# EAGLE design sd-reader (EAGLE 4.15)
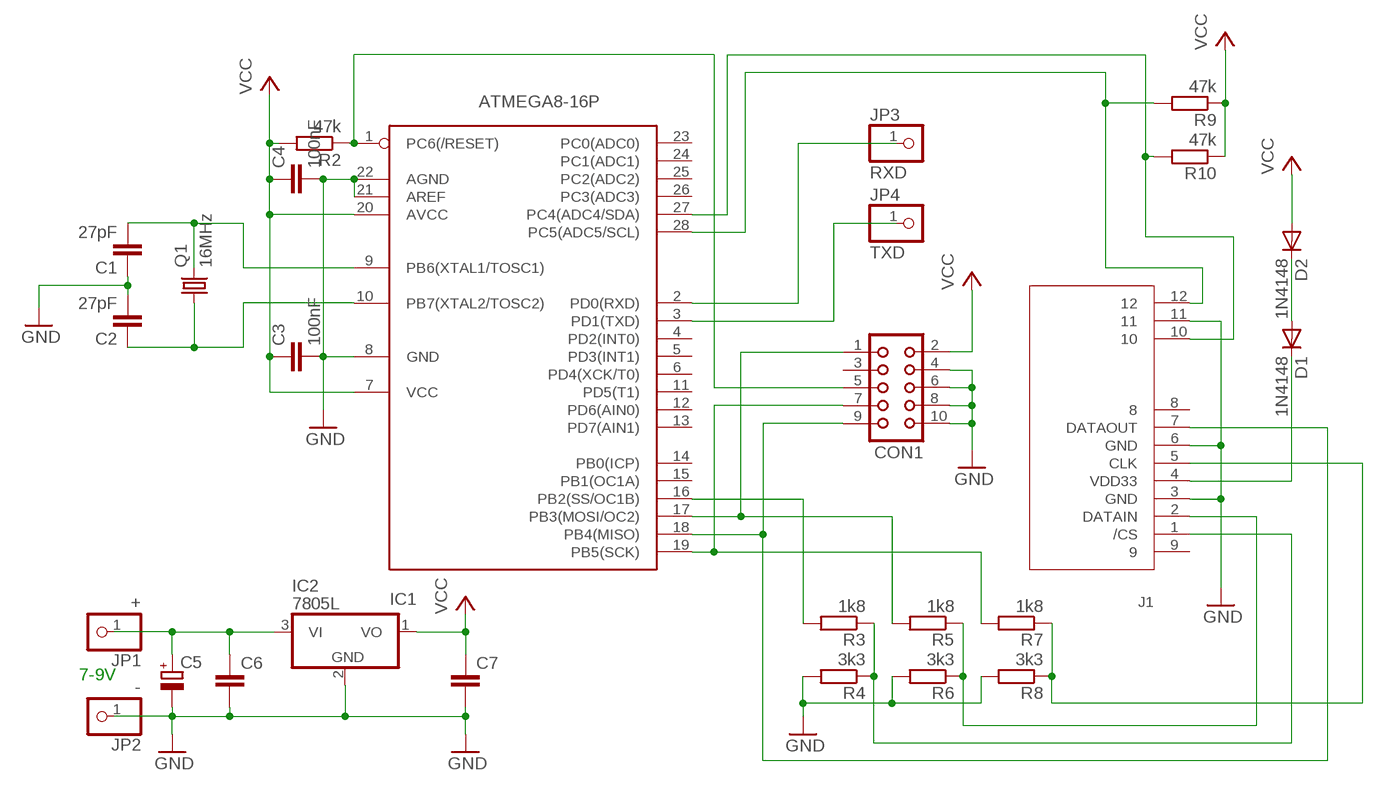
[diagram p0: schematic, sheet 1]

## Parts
C1  27pF  C-EU025-025X050  [C025-025X050]
C2  27pF  C-EU025-025X050  [C025-025X050]
C3  100nF  C-EU025-025X050  [C025-025X050]
C4  100nF  C-EU025-025X050  [C025-025X050]
C5  CPOL-EUE2.5-5  [E2,5-5]
C6  C-EU025-025X050  [C025-025X050]
C7  C-EU025-025X050  [C025-025X050]
CON1  CON10  [CON10]
D1  1N4148  [DO35-10]
D2  1N4148  [DO35-10]
IC1  ATMEGA8-16P  [DIL28-3]
IC2  7805L  [TO92]
J1  MMC_SOCK  [MMC_SOCK]
JP1  +  PINHD-1X1  [1X01]
JP2  -  PINHD-1X1  [1X01]
JP3  RXD  PINHD-1X1  [1X01]
JP4  TXD  PINHD-1X1  [1X01]
Q1  16MHz  CRYTALHC49U-V  [HC49U-V]
R2  47k  R-EU_0309/10  [0309/10]
R3  1k8  R-EU_0309/10  [0309/10]
R4  3k3  R-EU_0309/10  [0309/10]
R5  1k8  R-EU_0309/10  [0309/10]
R6  3k3  R-EU_0309/10  [0309/10]
R7  1k8  R-EU_0309/10  [0309/10]
R8  3k3  R-EU_0309/10  [0309/10]
R9  47k  R-EU_0309/10  [0309/10]
R10  47k  R-EU_0309/10  [0309/10]

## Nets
GND: C1.1 C2.2 C3.2 C4.2 C5.- C6.2 C7.2 CON1.4 CON1.6 CON1.8 CON1.10 IC1.8(GND) IC1.21(AREF) IC1.22(AGND) IC2.2(GND) J1.3(GND) J1.6(GND) J1.11 JP2.1 R4.2 R6.2 R8.2
N$1: D1.C J1.4(VDD33)
N$2: D1.A D2.C
N$3: CON1.9 IC1.18(PB4(MISO)) J1.7(DATAOUT)
N$4: CON1.1 IC1.17(PB3(MOSI/OC2)) R5.2
N$5: C1.2 IC1.9(PB6(XTAL1/TOSC1)) Q1.2
N$6: C2.1 IC1.10(PB7(XTAL2/TOSC2)) Q1.1
N$7: J1.1(/CS) R3.1 R4.1
N$8: CON1.7 IC1.19(PB5(SCK)) R7.2
N$9: CON1.5 IC1.1(PC6(/RESET)) R2.1
N$10: IC1.16(PB2(SS/OC1B)) R3.2
N$11: J1.2(DATAIN) R5.1 R6.1
N$12: J1.5(CLK) R7.1 R8.1
N$13: IC1.2(PD0(RXD)) JP3.1
N$14: C5.+ C6.1 IC2.3(VI) JP1.1
N$15: IC1.3(PD1(TXD)) JP4.1
N$16: IC1.28(PC5(ADC5/SCL)) J1.12 R9.2
N$17: IC1.27(PC4(ADC4/SDA)) J1.10 R10.2
VCC: C3.1 C4.1 C7.1 CON1.2 D2.A IC1.7(VCC) IC1.20(AVCC) IC2.1(VO) R2.2 R9.1 R10.1
Unconnected: CON1.3 IC1.4(PD2(INT0)) IC1.5(PD3(INT1)) IC1.6(PD4(XCK/T0)) IC1.11(PD5(T1)) IC1.12(PD6(AIN0)) IC1.13(PD7(AIN1)) IC1.14(PB0(ICP)) IC1.15(PB1(OC1A)) IC1.23(PC0(ADC0)) IC1.24(PC1(ADC1)) IC1.25(PC2(ADC2)) IC1.26(PC3(ADC3)) J1.8 J1.9

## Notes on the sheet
- 7-9V

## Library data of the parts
C1-C4 C6 C7 = rcl:C-EU: CAPACITOR, European symbol
C5 = rcl:CPOL-EU: POLARIZED CAPACITOR, European symbol
CON1 = con-harting:CON10: CONNECTOR
D1 D2 = diode:1N4148: DIODE
IC1 = avr:ATMEGA8*P: MICROCONTROLLER 8 Kbytes FLASH 1 kbytes SRAM 512 bytes EEPROM USART 4-channel 10 bit ADC 2-channel 8 bit ADC
IC2 = linear:78*: Positive VOLTAGE REGULATOR Source: http://cache.national.com/ds/LM/LM78L05.pdf http://www.fairchildsemi.com/ds/LM/LM7805.pdf
J1 = mmc_sd_card:MMC_SOCK: MMC/SD Card Connector
JP1-JP4 = pinhead:PINHD-1X1: PIN HEADER
Q1 = crystal:CRYTAL: CRYSTAL
R2-R10 = rcl:R-EU_: RESISTOR, European symbol

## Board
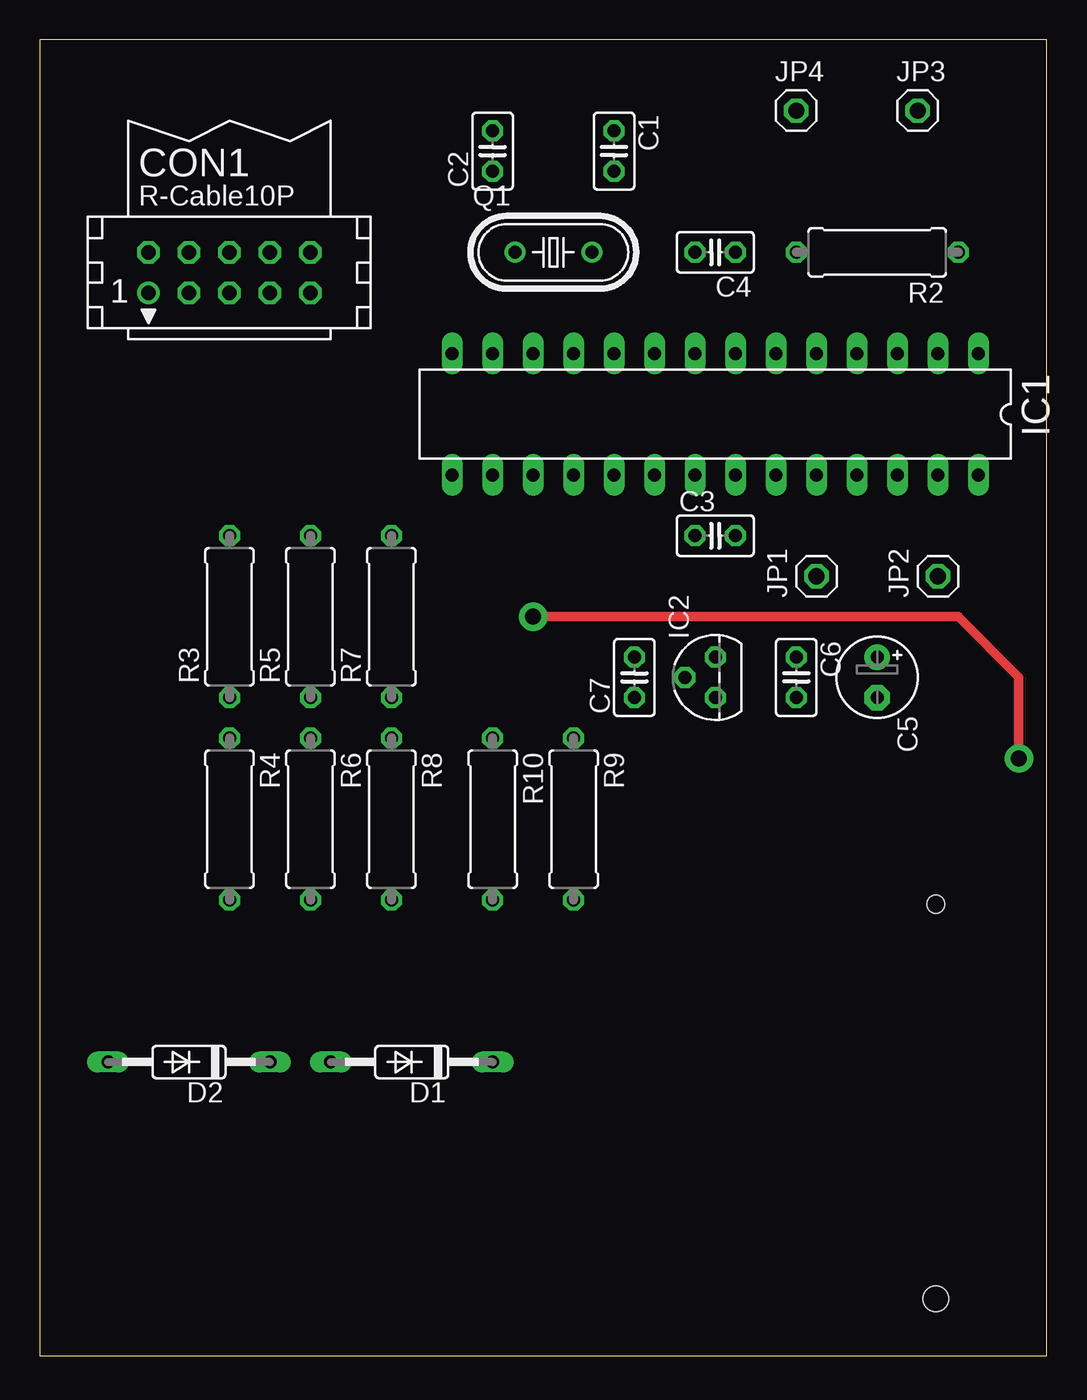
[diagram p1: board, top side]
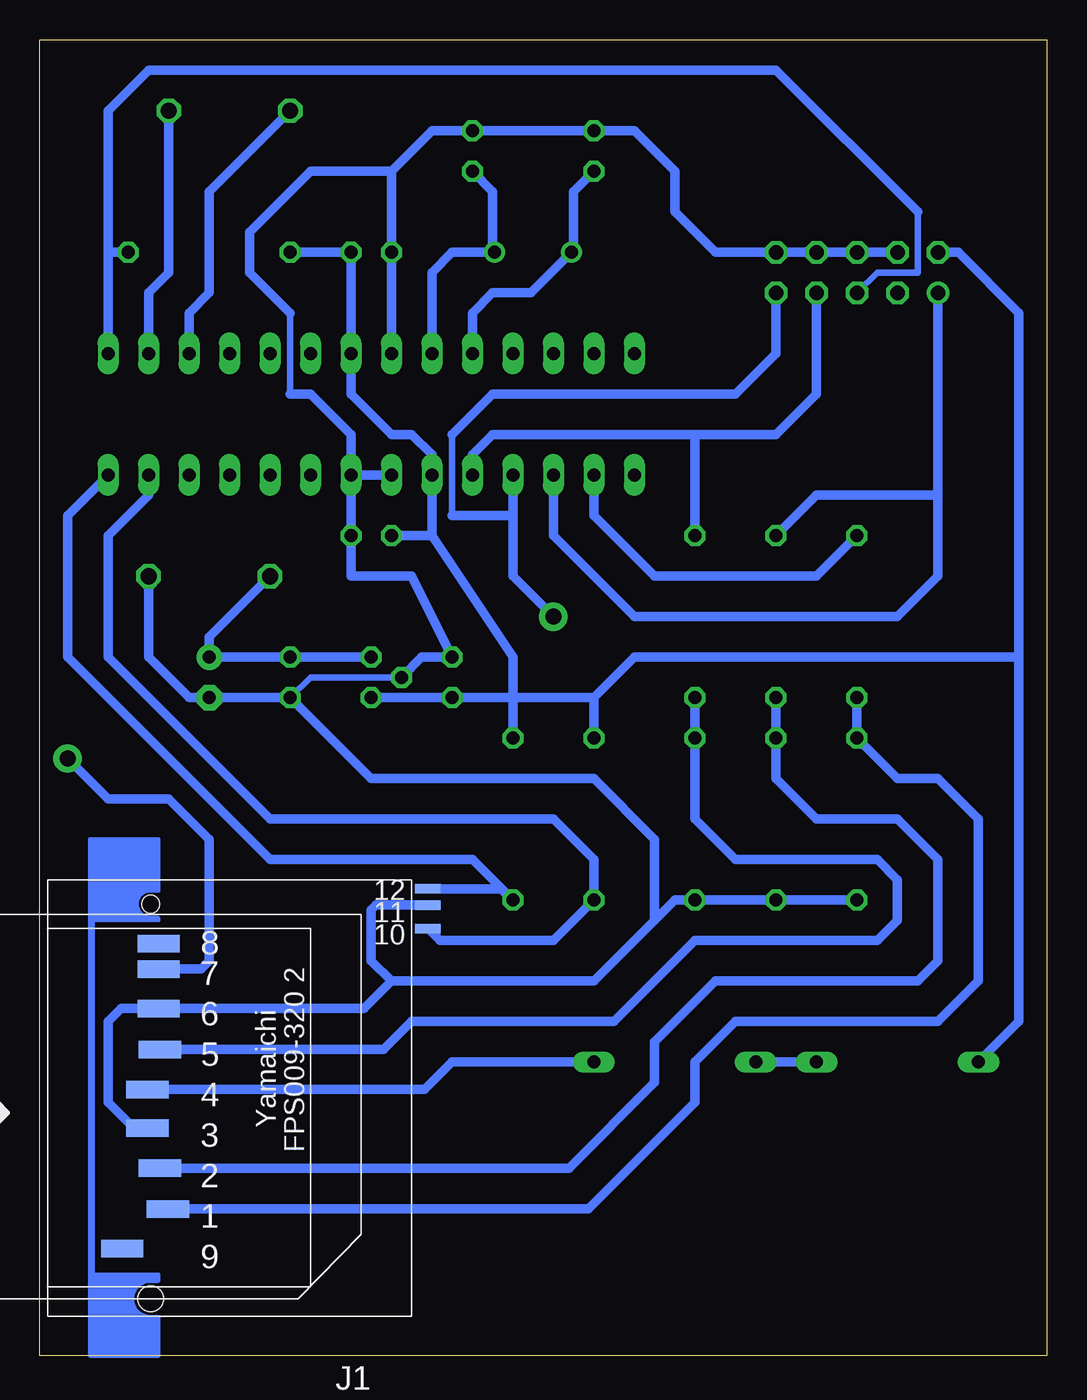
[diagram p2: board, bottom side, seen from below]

Size 63.17 x 82.54 mm. Coordinates in mm from the lower left corner, seen from the top.
Outline: 0,0 63.17,0 63.17,82.54 0,82.54 0,0
Copper layers (1*16): Top 0.035mm / dielectric 1.5mm / Bottom 0.035mm
Design rules "default": minimum track width 10mil, minimum drill 24mil, track to track 8mil, track to pad 8mil, pad to pad 8mil, via to via 8mil, smd to smd 8mil, copper to edge 40mil, drill to drill 8mil, minimum pad ring 10mil, minimum via ring 8mil, stop-mask expansion 4mil, vias tented up to drill 0mil, thermal gap 10mil

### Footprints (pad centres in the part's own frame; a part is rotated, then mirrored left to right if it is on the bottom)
C025-025X050 = drill 0.813 octagon: 1 -1.27,0; 2 1.27,0
E2,5-5 = drill 0.813 pad 1.6 round: + -1.27,0 | drill 0.813 pad 1.6 octagon: - 1.27,0
CON10 = drill 0.914 round: 1 -5.08,-1.27 | drill 0.914 octagon: 2 -5.08,1.27; 3 -2.54,-1.27; 4 -2.54,1.27; 5 0,-1.27; 6 0,1.27; 7 2.54,-1.27; 8 2.54,1.27; 9 5.08,-1.27; 10 5.08,1.27
DO35-10 = drill 0.813 long: A 5.08,0; C -5.08,0
DIL28-3 = drill 0.813 long: 1 -16.51,-3.81; 2 -13.97,-3.81; 3 -11.43,-3.81; 4 -8.89,-3.81; 5 -6.35,-3.81; 6 -3.81,-3.81; 7 -1.27,-3.81; 8 1.27,-3.81; 9 3.81,-3.81; 10 6.35,-3.81; 11 8.89,-3.81; 12 11.43,-3.81; 13 13.97,-3.81; 14 16.51,-3.81; 15 16.51,3.81; 16 13.97,3.81; 17 11.43,3.81; 18 8.89,3.81; 19 6.35,3.81; 20 3.81,3.81; 21 1.27,3.81; 22 -1.27,3.81; 23 -3.81,3.81; 24 -6.35,3.81; 25 -8.89,3.81; 26 -11.43,3.81; 27 -13.97,3.81; 28 -16.51,3.81
TO92 = drill 0.813 octagon: 1 -1.27,0; 2 0,1.905; 3 1.27,0
MMC_SOCK = smd 2.65 x 1.1: 1 15.291,20.65; 2 15.799,18.085; 3 16.586,15.57; 4 16.586,13.157; 5 15.799,10.643; 6 15.875,8.077; 7 15.875,5.588; 8 15.875,3.988; 9 18.161,23.139 | smd 1.6 x 0.6: 10 -1.016,3.048; 11 -1.016,1.575; 12 -1.016,0.559 | hole 1.1: 16.383,1.524 | hole 1.6: 16.383,26.289
1X01 = drill 1.016 octagon: 1 0,0
HC49U-V = drill 0.813 round: 1 -2.413,0; 2 2.413,0
0309/10 = drill 0.813 octagon: 1 -5.08,0; 2 5.08,0

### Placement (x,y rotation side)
C1  36.03,75.56 270 top
C2  28.41,75.56 90 top
C3  42.38,51.43 0 top
C4  42.38,69.21 180 top
C5  52.54,42.54 270 top
C6  47.46,42.54 270 top
C7  37.3,42.54 90 top
CON1  11.9,67.94 0 top
D1  23.33,18.41 180 top
D2  9.36,18.41 180 top
IC1  42.38,59.05 180 top
IC2  42.38,42.54 90 top
J1  39.84,29.84 180 bottom
JP1  48.73,48.89 90 top
JP2  56.35,48.89 90 top
JP3  55.08,78.1 0 top
JP4  47.46,78.1 0 top
Q1  32.22,69.21 0 top
R2  52.54,69.21 180 top
R3  11.9,46.35 90 top
R4  11.9,33.65 270 top
R5  16.98,46.35 90 top
R6  16.98,33.65 270 top
R7  22.06,46.35 90 top
R8  22.06,33.65 270 top
R9  33.49,33.65 270 top
R10  28.41,33.65 270 top

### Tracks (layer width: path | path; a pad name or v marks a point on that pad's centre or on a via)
GND
  Bottom 0.406: IC2.2 46.19,42.54 C6.2 | 47.46,60.32 47.46,65.4
  Bottom 0.61: CON1.4 CON1.6 CON1.8 CON1.10 20.79,69.21 23.33,71.75 23.33,74.29 25.87,76.83 C2.2 C1.1 38.57,76.83 41.11,74.29 | JP2.1 56.35,43.81 53.81,41.27 C5.- C6.2 42.38,36.19 28.41,36.19 24.6,32.38 24.6,27.3 | IC1.8 C4.2 41.11,74.29 | IC1.22 C3.2 43.65,48.89 39.84,48.89 C7.2 39.2,43.81 IC2.2 | IC1.22 43.65,57.78 46.19,60.32 47.46,60.32 | 47.46,65.4 50,67.94 50,70.48 46.19,74.29 41.11,74.29 | IC1.22 IC1.21 | J1.11 42.07,28.27 42.38,27.96 42.38,24.76 41.11,23.49 | R4.2 R6.2 R8.2 23.33,28.57 24.6,27.3 | J1.3 57.29,14.27 58.89,15.87 58.89,20.95 58.08,21.76 J1.6 42.84,21.76 41.11,23.49 | 41.11,23.49 28.41,23.49 24.6,27.3
N$1
  Bottom 0.61: J1.4 39.03,16.68 37.3,18.41 D1.C
N$2
  Bottom 0.61: D2.C D1.A
N$3  (via drill 1 pad 1.78)
  Top 0.61: v61.43,37.46 61.43,42.54 57.62,46.35 v30.95,46.35
  Bottom 0.406: 37.3,52.7 37.3,57.78
  Bottom 0.61: CON1.9 16.98,62.86 19.52,60.32 34.76,60.32 37.3,57.78 | 33.49,52.7 37.3,52.7 | v61.43,37.46 58.89,34.92 55.08,34.92 52.54,32.38 52.54,24.76 53.05,24.25 J1.7 | v30.95,46.35 33.49,48.89 33.49,52.7 | 33.49,52.7 IC1.18
N$4
  Bottom 0.61: IC1.17 30.95,51.43 25.87,46.35 9.36,46.35 6.82,48.89 6.82,53.97 | 6.82,53.97 CON1.1 | R5.2 14.44,53.97 6.82,53.97
N$5
  Bottom 0.61: IC1.9 38.57,67.94 37.3,69.21 34.89,69.21 34.76,69.08 Q1.2 34.76,69.21 34.76,73.02 C1.2
N$6
  Bottom 0.61: IC1.10 36.03,65.4 34.76,66.67 32.35,66.67 Q1.1 29.68,69.21 29.68,73.02 C2.1
N$7
  Bottom 0.61: J1.1 28.74,9.19 22.06,15.87 22.06,18.41 19.52,20.95 6.82,20.95 4.28,23.49 4.28,33.65 6.82,36.19 9.36,36.19 R4.1 R3.1
N$8
  Bottom 0.61: CON1.7 14.44,60.32 16.98,57.78 22.06,57.78 | IC1.19 36.03,56.51 34.76,57.78 22.06,57.78 | R7.2 22.06,57.78
N$9
  Bottom 0.406: CON1.5 10.63,67.94 8.09,67.94 8.09,71.75
  Bottom 0.61: 58.89,69.21 IC1.1 | 8.09,71.75 16.98,80.64 56.35,80.64 58.89,78.1 58.89,69.21 | 58.89,69.21 R2.1
N$10
  Bottom 0.61: IC1.16 28.41,52.7 24.6,48.89 14.44,48.89 R3.2
N$11
  Bottom 0.61: J1.2 29.98,11.76 24.6,17.14 24.6,19.68 20.79,23.49 8.09,23.49 6.82,24.76 6.82,31.11 9.36,33.65 14.44,33.65 16.98,36.19 R6.1 R5.1
N$12
  Bottom 0.61: J1.5 41.59,19.2 39.84,20.95 27.14,20.95 22.06,26.03 10.63,26.03 9.36,27.3 9.36,29.84 10.63,31.11 19.52,31.11 22.06,33.65 R8.1 R7.1
N$13
  Bottom 0.61: IC1.2 56.35,66.67 55.08,67.94 JP3.1
N$14
  Bottom 0.61: JP1.1 52.54,45.08 C5.+ C6.1 IC2.3
N$15
  Bottom 0.61: IC1.3 53.81,65.4 52.54,66.67 52.54,73.02 JP4.1
N$16
  Bottom 0.61: IC1.28 61.43,52.7 61.43,43.81 48.73,31.11 36.03,31.11 R9.2 34.2,29.28 J1.12
N$17
  Bottom 0.61: IC1.27 56.35,53.97 58.89,51.43 58.89,43.81 48.73,33.65 30.95,33.65 28.41,31.11 R10.2 30.95,26.03 38.06,26.03 J1.10
VCC
  Bottom 0.61: R2.2 C4.1 IC1.7 43.65,60.32 41.11,57.78 39.84,57.78 38.57,56.51 IC1.20 38.57,51.43 | CON1.2 5.55,69.21 1.74,65.4 1.74,43.81 | IC2.1 C7.1 33.49,41.27 | D2.A 1.74,20.95 1.74,43.81 | 1.74,43.81 25.87,43.81 28.41,41.27 | 28.41,41.27 33.49,41.27 | 38.57,51.43 C3.1 | 38.57,51.43 33.49,43.81 33.49,41.27 | 28.41,41.27 R10.1 | 33.49,41.27 R9.1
